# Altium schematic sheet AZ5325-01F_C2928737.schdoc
size 127 x 101 mm
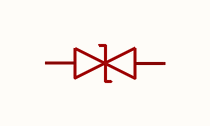
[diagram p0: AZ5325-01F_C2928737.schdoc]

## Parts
U?  az5325-01f_c2928737  [DFN1006-2L-BI]  (value not drawn)

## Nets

Not connected (* = marked no-connect by the designer): U? 1 2

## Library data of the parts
U? = az5325-01f_c2928737: 极性:双向;反向截止电压(Vrwm):5V;钳位电压:9V；15V;峰值脉冲功率(Ppp):-;击穿电压:9V;; Manufacturer: TECH PUBLIC(台舟); AddInBom: yes; ModelId: 2bdbcca3b35b49c5a8ae725a08658930; ModelTransform: 40.1574,24.4094,0,0,0,0,0,0,0; Polarity: 双向; Reverse Stand-Off Voltage (Vrwm): 5V; Clamping Voltage: 9V；15V; Voltage - Breakdown: 9V; Reverse Leakage Current (Ir): 80nA; Number of Channels: 单路; level of protection: IEC 61000-4-5；IEC 61000-4-2; Junction Capacitance: 0.6pF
